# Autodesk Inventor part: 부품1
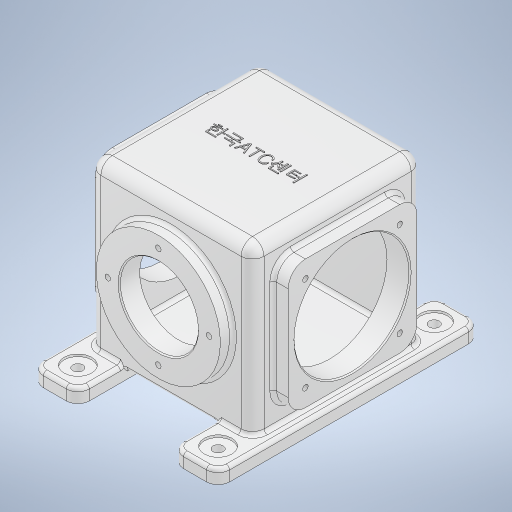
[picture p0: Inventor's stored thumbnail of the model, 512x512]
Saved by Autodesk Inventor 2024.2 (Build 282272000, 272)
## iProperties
Created: 2026-01
Part Number: 부품1
Material: 알루미늄 6061
Document SubType Name: Modeling
Designer: home
Density: 2.7 g/cm^3
Appearance: 알루미늄 - 평지
Mass: 2675.29 g
Surface Area: 2461.71 cm^2
Volume: 990.847 cm^3
Author: home
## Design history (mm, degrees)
sketch "스케치1"
  geometry: L1 (81, -114)-(41, -114); L2 (41, -114)-(41, 114); L3 (41, 114)-(81, 114); L4 (81, 114)-(81, -114); L5 (-41, -114)-(-81, -114); L6 (-81, -114)-(-81, 114); L7 (-81, 114)-(-41, 114); L8 (-41, 114)-(-41, -114); 3 further points
  constraints: 16 end point, 4 parallel, 2 horizontal, 2 horizontal alignment, 2 midpoint, 2 perpendicular
  dimensions: "d0" = 228 distance of L3.end L1.start; "d1" = 228 distance of L5.end L6.end; "d2" = 81 distance from line of point (0, 0) L4; "d3" = 81 distance from line of point (0, 0) L6; "d4" = 40 distance of L1.start L1.end; "d5" = 40 distance of L5.start L5.end
extrude "돌출1" new body sketch "스케치1" distance "d6" = 12; taper "d7" = 0 deg
sketch "스케치2"
  geometry: L1 (-130.405, 82)-(130.405, 82); L2 (-71, 9)-(71, 9); L3 (71, 9)-(71, 155); L4 (71, 155)-(-71, 155); L5 (-71, 155)-(-71, 9); L6 (-71, 9)-(71, 155); L7 (71, 9)-(-71, 155); 2 further points
  constraints: 14 end point, 3 midpoint, 2 horizontal, 2 parallel, 1 perpendicular, 1 vertical alignment
  dimensions: "d8" = 82 distance from line of point (0, 0) L1; "d9" = 142 distance of L3.end L4.end; "d10" = 146 distance of L2.end L3.end
extrude "돌출2" join sketch "스케치2" stored distance "d11" = 148; taper "d12" = 0 deg
sketch "스케치4"
  geometry: L1 (71, 12)-(41, 12) reference; L2 (71, 12)-(71, 155) reference; L3 (71, 155)-(-71, 155) reference; L4 (-71, 155)-(-71, 12) reference; L5 (-41, 12)-(-71, 12) reference; L6 (-41, 9)-(-41, 12) reference; L7 (-41, 9)-(41, 9) reference; L8 (41, 12)-(41, 9) reference; C1 r 54 at (0, 82); 1 further point
  constraints: 1 centre point
  dimensions: "d14" = 108 diameter of C1; "d15" = 82 distance of point (0, 0) C1.centre
extrude "돌출3" join sketch "스케치4" distance "d16" = 11; taper "d17" = 0 deg
sketch "스케치5"
  geometry: L1 (-130, 14)-(-18, 14); L2 (-18, 14)-(-18, 126); L3 (-18, 126)-(-130, 126); L4 (-130, 126)-(-130, 14); L5 (-130, 14)-(-18, 126); L6 (-18, 14)-(-130, 126); L7 (-188, -12)-(40, -12) reference; 4 further points
  constraints: 12 end point, 4 midpoint, 2 parallel, 1 horizontal, 1 perpendicular, 1 vertical alignment
  dimensions: "d18" = 82 distance of point (-74, -12) point (-74, 70); "d19" = 112 distance of L2.end L3.end; "d20" = 112 distance of L1.end L2.end
extrude "돌출4" join sketch "스케치5" distance "d21" = 13; taper "d22" = 0 deg
sketch "스케치6"
  geometry: L1 (71, 155)-(-71, 155) reference; L2 (71, 12)-(41, 12) reference; L3 (71, 12)-(71, 155) reference; L4 (71, 155)-(-71, 155) reference; L5 (-71, 155)-(-71, 12) reference; L6 (-41, 12)-(-71, 12) reference; L7 (-41, 9)-(-41, 12) reference; L8 (-41, 9)-(41, 9) reference; L9 (41, 12)-(41, 9) reference; L10 (-71, 155)-(-71, 12) reference; L11 (-64, 16)-(64, 16); L12 (64, 16)-(64, 148); L13 (64, 148)-(-64, 148); L14 (-64, 148)-(-64, 16); L15 (-64, 16)-(64, 148); L16 (64, 16)-(-64, 148); C1 r 54 at (0, 82) reference; 1 further point
  constraints: 12 end point, 2 midpoint, 2 parallel, 1 horizontal, 1 perpendicular
  dimensions: "d23" = 7 distance between parallel lines of L13 L1; "d24" = 7 distance between parallel lines of L3 L12
extrude "돌출6" cut sketch "스케치6" stored distance "d27" = 134.5; taper "d28" = 0 deg
sketch "스케치7"
  geometry: L1 (82, 122.894)-(82, -126.18); L2 (136, 85)-(28, 85) reference; L3 (148, 67.25)-(16, 67.25) reference; L4 (82, 85)-(116, 85); L5 (116, 85)-(116, 67.25); L6 (116, 67.25)-(82, 67.25); L7 (82, 67.25)-(82, 85); 4 further points
  constraints: 10 end point, 2 parallel, 1 horizontal, 1 midpoint, 1 perpendicular, 1 point on line, 1 vertical
  dimensions: "d29" = 82 distance from line of point (0, 0) L1; "d30" = 68 diameter of L5 L1
revolve "회전1" sketch "스케치7" stored, may be unused: angle "d31" = 90 deg
node "작업 평면1"
sketch "스케치8"
  geometry: L1 (84, 56)-(84, -56) reference; L2 (64, -67.25)-(64, 67.25) reference; L3 (-64, 67.25)-(-64, -67.25) reference; L4 (-84, 56)-(-84, -56) reference; L5 (133.409, 0)-(-211.285, 0); L6 (84, -1.643)-(64, -1.643); L7 (64, -1.643)-(64, -50); L8 (64, -50)-(84, -50); L9 (84, -50)-(84, -1.643); L10 (-84, 0)-(-64, 0); L11 (-64, 0)-(-64, -50); L12 (-64, -50)-(-84, -50); L13 (-84, -50)-(-84, 0); 7 further points
  constraints: 18 end point, 5 point on line, 4 parallel, 3 horizontal, 2 perpendicular, 1 midpoint
  dimensions: "d33" = 100 diameter of L8 L5; "d34" = 100 diameter of L12 L5
revolve "회전2" sketch "스케치8" stored, may be unused: angle "d35" = 360 deg
fillet "모깎기1" dims "d36" = 10
sketch "스케치9"
  geometry: L1 (-41, -104)-(-41, -74) reference; L2 (-41, -74)-(-71, -74) reference; L3 (-71, -74)-(-71, 74) reference; L4 (-71, 74)-(-41, 74) reference; L5 (-41, 74)-(-41, 104) reference; L6 (-51, 114)-(-71, 114) reference; L7 (-81, 104)-(-81, -104) reference; L8 (-71, -114)-(-51, -114) reference; L9 (-71, -74)-(-71, 74) reference; L10 (71, -74)-(-71, -74) reference; L11 (71, 74)-(71, -74) reference; L12 (-71, 74)-(71, 74) reference; A1 r 10 centre (-51, -104) between (-51, -114) and (-41, -104) reference; A2 r 10 centre (-51, 104) between (-41, 104) and (-51, 114) reference; A3 r 10 centre (-71, 104) between (-71, 114) and (-81, 104) reference; A4 r 10 centre (-71, -104) between (-81, -104) and (-71, -114) reference; 5 further points
  dimensions: "d37" = 94 vertical distance of point (0, 0) point (61, 94); "d38" = 94 vertical distance of point (0, 0) point (61, -94); "d39" = 94 vertical distance of point (0, 0) point (-61, 94); "d40" = 94 vertical distance of point (0, 0) point (-61, -94); "d41" = 61 horizontal distance of point (0, 0) point (-61, -94); "d42" = 61 horizontal distance of point (0, 0) point (61, -94); "d43" = 61 horizontal distance of point (0, 0) point (-61, 94); "d44" = 61 horizontal distance of point (0, 0) point (61, 94)
hole "구멍1" sketch "스케치9" at (-61, 94), (61, 94), (-61, -94), (61, -94) diameter "d45" = 9; stored, may be unused: countersink angle "d49" = 90 deg, drill point angle "d51" = 0 deg; dims "d46" = 16, "d47" = 24, "d48" = 2, "d50" = 18
sketch "스케치10"
  geometry: C1 r 54 at (0, 0) reference; A1 r 44 centre (0, 0) between (0, 44) and (-44, 0); 3 further points
  constraints: 4 point on circle, 1 centre point, 1 coincident
  dimensions: "d52" = 88 diameter of A1
hole "구멍2" sketch "스케치10" at (0, 44), (-44, 0), (0, -44), (44, 0) diameter "d53" = 4.917; stored, may be unused: countersink angle "d57" = 90 deg, drill point angle "d59" = 118 deg; dims "d54" = 12, "d55" = 24, "d56" = 2, "d58" = 14
sketch "스케치11"
  geometry: L1 (-115, 29)-(-33, 29); L2 (-33, 29)-(-33, 111); L3 (-33, 111)-(-115, 111); L4 (-115, 111)-(-115, 29); L5 (-115, 29)-(-33, 111); L6 (-33, 29)-(-115, 111); C1 r 50 at (-74, 70) reference; 5 further points
  constraints: 12 end point, 4 coincident, 2 midpoint, 2 parallel, 1 horizontal, 1 perpendicular
  dimensions: "d60" = 82 distance of L2.end L3.end; "d61" = 82 distance of L1.end L2.end
hole "구멍3" sketch "스케치11" at (-115, 111), (-115, 29), (-33, 29), (-33, 111) diameter "d62" = 4.917; stored, may be unused: countersink angle "d66" = 90 deg, drill point angle "d68" = 118 deg; dims "d63" = 12, "d64" = 4, "d65" = 2, "d67" = 14
fillet "모깎기2" dims "d69" = 10
fillet "모깎기3" dims "d70" = 10
fillet "모깎기4" dims "d71" = 3
fillet "모깎기5" dims "d72" = 3
fillet "모깎기6" dims "d73" = 3
fillet "모깎기7" dims "d74" = 3
chamfer "모따기1" distance "d75" = 1; stored, may be unused: second distance "d76" = 2, angle "d77" = 45 deg
chamfer "모따기2" distance "d78" = 1; stored, may be unused: second distance "d79" = 2, angle "d80" = 45 deg
fillet "모깎기8" dims "d81" = 15
fillet "모깎기9" dims "d82" = 3
fillet "모깎기10" dims "d83" = 15
fillet "모깎기11" dims "d84" = 3
fillet "모깎기12" dims "d85" = 3
sketch "스케치12"
  geometry: L1 (19.521, -57.996)-(102.479, -57.996); L2 (102.479, -57.996)-(102.479, -70.004); L3 (102.479, -70.004)-(19.521, -70.004); L4 (19.521, -70.004)-(19.521, -57.996); 3 further points
  constraints: 2 midpoint, 1 horizontal alignment, 1 vertical alignment, 2 other
feature "엠보싱1" sketch "스케치12" dims "d86" = 0.5, "d87" = 0
fillet "모깎기13" dims "d88" = 3
node "작업 평면2"
node "솔리드1"
mirror "미러1"
mirror "미러2"
node "투영된 루프2"
node "투영된 루프3"
node "투영된 루프4"
node "투영된 루프5"
feature "A9D066F2-1C7D-4E18-AEED-F7BC21143FA4" dims "d45" = 9, "d46" = 16, "d47" = 24, "d48" = 2, "d49" = 90 deg, "d50" = 18, "d51" = 0
other parameters: "d32" = 82, "d89" = 94.25
